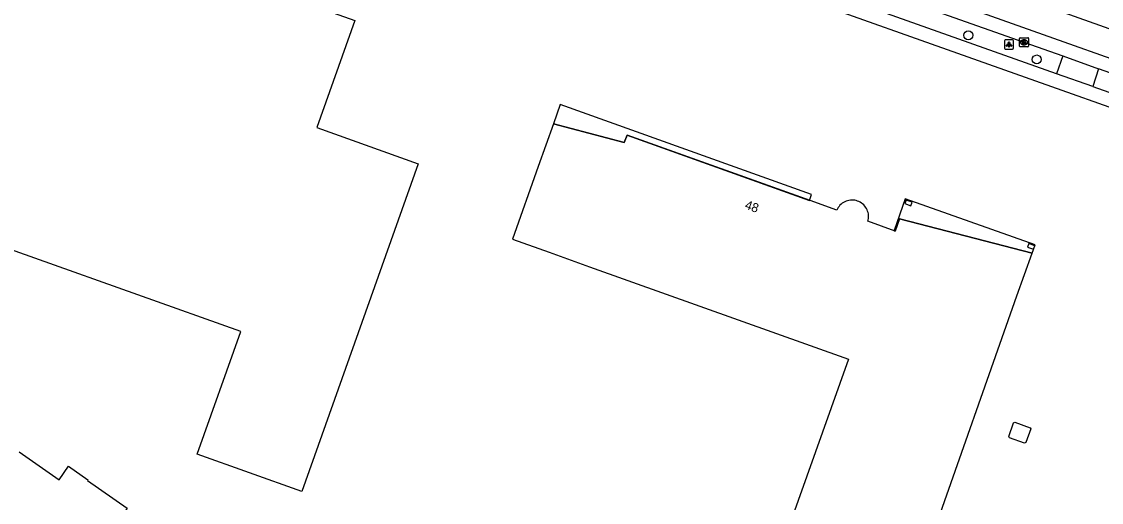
# Model space of a CAD drawing. Extents: x 155018 to 156648, y 383980 to 385733.
# Drawn here: x 155544.9 to 155664.5, y 385117.1 to 385170.3 of the extents above; entities that cross this region are included whole.
import ezdxf

# ---------------------------------------------------------------- set-up
doc = ezdxf.new("R2010")
doc.units = 0
for name, color, linetype in [('IMGEO_Boom', 7, 'Continuous'), ('IMGEO_Kolk', 7, 'Continuous'), ('IMGEO_Lage_trafo', 7, 'Continuous'), ('IMGEO_Lichtpunt', 7, 'Continuous'), ('IMGEO_OVBaan_gesloten', 7, 'Continuous'), ('IMGEO_Pand', 7, 'Continuous'), ('IMGEO_Pand_nummerreeks', 7, 'Continuous'), ('IMGEO_Pand_overbouw', 7, 'Continuous'), ('IMGEO_Rijbaan_lokaal_gesloten', 7, 'Continuous'), ('IMGEO_Rijbaan_lokaal_open', 7, 'Continuous'), ('IMGEO_Voetpad_open', 7, 'Continuous')]:
    doc.layers.add(name, color=color, linetype=linetype)

msp = doc.modelspace()

# ---------------------------------------------------------------- linework, layer by layer
at = {"layer": 'IMGEO_Boom'}
for centre in [(155649.75, 385168.83), (155657.32, 385166.16)]:
    msp.add_circle(centre, 0.489, dxfattribs=at)
at = {"layer": 'IMGEO_Kolk'}
for p, q in [((155655.41, 385167.63), (155655.41, 385168.49)), ((155655.49, 385168.56), (155656.34, 385168.56)), ((155656.34, 385167.56), (155655.49, 385167.56)), ((155655.9, 385168.34), (155655.93, 385168.34)), ((155655.92, 385167.78), (155655.9, 385167.78)), ((155656.41, 385168.49), (155656.41, 385167.63))]:
    msp.add_line(p, q, dxfattribs=at)
for points in [[(155655.41, 385167.63), (155655.41, 385168.49)], [(155655.49, 385168.56), (155656.34, 385168.56)], [(155656.34, 385167.56), (155655.49, 385167.56)], [(155655.73, 385168.26), (155655.86, 385168.26), (155655.86, 385168.11), (155655.99, 385168.26), (155656.15, 385168.26), (155656.01, 385168.11), (155656.16, 385167.86), (155656.01, 385167.86), (155655.92, 385168.02), (155655.86, 385167.96), (155655.86, 385167.86), (155655.73, 385167.86), (155655.73, 385168.26)], [(155656.41, 385168.49), (155656.41, 385167.63)]]:
    msp.add_lwpolyline(points, dxfattribs=at)
for centre, start, end in [((155655.49, 385168.48), 91.552, 178.448), ((155655.49, 385168.48), 91.552, 178.448), ((155655.49, 385167.63), 181.552, 268.448), ((155655.49, 385167.63), 181.552, 268.448), ((155656.34, 385168.48), 1.552, 88.448), ((155656.34, 385168.48), 1.552, 88.448), ((155656.34, 385167.63), 271.552, 358.448), ((155656.34, 385167.63), 271.552, 358.448)]:
    msp.add_arc(centre, 0.0765, start, end, dxfattribs=at)
for centre, major_axis, ratio, start_param, end_param in [((155655.9, 385168.06), (-0.387, 0.002), 0.722429, 4.712389, 7.853982), ((155655.92, 385168.06), (-0.39, 0.002), 0.717154, 1.570796, 4.712389)]:
    msp.add_ellipse(centre, major_axis=major_axis, ratio=ratio, start_param=start_param, end_param=end_param, dxfattribs=at)
at = {"layer": 'IMGEO_Lage_trafo'}
msp.add_lwpolyline([(155655.98, 385123.68), (155654.3, 385124.27), (155654.22, 385124.42), (155654.75, 385125.91), (155654.91, 385125.99), (155656.6, 385125.37), (155656.66, 385125.24), (155656.12, 385123.74), (155655.98, 385123.68)], dxfattribs=at)
at = {"layer": 'IMGEO_Lichtpunt'}
for p, q in [((155653.75, 385168.22), (155653.75, 385167.41)), ((155653.75, 385168.22), (155653.75, 385167.41)), ((155654.65, 385168.31), (155653.84, 385168.31)), ((155654.65, 385168.31), (155653.84, 385168.31)), ((155654.74, 385167.41), (155654.74, 385168.22)), ((155654.74, 385167.41), (155654.74, 385168.22)), ((155653.84, 385167.31), (155654.65, 385167.31)), ((155653.84, 385167.31), (155654.65, 385167.31))]:
    msp.add_line(p, q, dxfattribs=at)
for points in [[(155654.12, 385167.88), (155654.16, 385167.85), (155653.97, 385167.59), (155653.93, 385167.62), (155654.12, 385167.88)], [(155654.22, 385167.83), (155654.27, 385167.83), (155654.27, 385167.51), (155654.22, 385167.51), (155654.22, 385167.83)], [(155654.33, 385167.85), (155654.37, 385167.88), (155654.56, 385167.62), (155654.52, 385167.59), (155654.33, 385167.85)]]:
    msp.add_lwpolyline(points, dxfattribs=at)
msp.add_circle((155654.25, 385168.01), 0.0994, dxfattribs=at)
for centre, start, end in [((155653.84, 385168.22), 90, 180), ((155653.84, 385168.22), 90, 180), ((155653.84, 385167.41), 180, 270), ((155653.84, 385167.41), 180, 270), ((155654.65, 385168.22), 0, 90), ((155654.65, 385168.22), 0, 90), ((155654.65, 385167.41), 270, 0), ((155654.65, 385167.41), 270, 360)]:
    msp.add_arc(centre, 0.0946, start, end, dxfattribs=at)
at = {"layer": 'IMGEO_OVBaan_gesloten'}
msp.add_lwpolyline([(155740.67, 385142.78), (155686.14, 385162.15), (155622.86, 385184.67)], dxfattribs=at)
at = {"layer": 'IMGEO_Pand'}
for points in [[(155564.35, 385122.44), (155569.18, 385136.03), (155534.94, 385148.2), (155545.92, 385179.11), (155547.38, 385178.75), (155551.81, 385178.73), (155553.29, 385178.36), (155554, 385180.39), (155574.93, 385172.93), (155575.01, 385172.91), (155581.82, 385170.48), (155577.59, 385158.61), (155588.82, 385154.6), (155575.94, 385118.32), (155564.35, 385122.44)], [(155656.82, 385144.69), (155642.14, 385148.51), (155641.65, 385147.16), (155638.63, 385148.24), (155638.67, 385148.4), (155638.69, 385148.56), (155638.7, 385148.72), (155638.7, 385148.89), (155638.68, 385149.05), (155638.64, 385149.21), (155638.59, 385149.36), (155638.53, 385149.51), (155638.46, 385149.66), (155638.37, 385149.79), (155638.27, 385149.92), (155638.16, 385150.04), (155638.04, 385150.15), (155637.91, 385150.25), (155637.77, 385150.34), (155637.63, 385150.41), (155637.48, 385150.48), (155637.33, 385150.52), (155637.17, 385150.56), (155637, 385150.58), (155636.84, 385150.58), (155636.68, 385150.57), (155636.52, 385150.55), (155636.36, 385150.51), (155636.21, 385150.46), (155636.06, 385150.4), (155635.91, 385150.32), (155635.78, 385150.23), (155635.65, 385150.13), (155635.53, 385150.02), (155635.43, 385149.89), (155635.33, 385149.76), (155635.25, 385149.62), (155635.18, 385149.48), (155632.25, 385150.52), (155611.95, 385157.79), (155611.64, 385156.96), (155603.8, 385159.03), (155602.12, 385154.32), (155599.26, 385146.25), (155603.32, 385144.81), (155607.79, 385143.21), (155636.49, 385132.98), (155624.37, 385098.99)], [(155643.51, 385150.35), (155642.85, 385150.58), (155642.73, 385150.2), (155643.39, 385149.96), (155643.51, 385150.35)], [(155645.5, 385112.59), (155655.13, 385139.98), (155656.82, 385144.69)], [(155657.1, 385145.53), (155656.44, 385145.76), (155656.3, 385145.38), (155656.96, 385145.15), (155657.1, 385145.53)], [(155544.65, 385122.72), (155549.06, 385119.62), (155550.12, 385121.11), (155552.26, 385119.62), (155552.2, 385119.53), (155556.6, 385116.46), (155537.67, 385089.36)]]:
    msp.add_lwpolyline(points, dxfattribs=at)
at = {"layer": 'IMGEO_Pand_overbouw'}
for points in [[(155603.8, 385159.03), (155611.64, 385156.96), (155611.95, 385157.79), (155632.16, 385150.55), (155632.39, 385151.21), (155604.56, 385161.17)], [(155641.52, 385147.21), (155641.65, 385147.16), (155642.14, 385148.51), (155656.82, 385144.69), (155657.15, 385145.62), (155642.76, 385150.74)]]:
    msp.add_lwpolyline(points, close=True, dxfattribs=at)
at = {"layer": 'IMGEO_Rijbaan_lokaal_gesloten'}
for points in [[(155557.9, 385204.57), (155590.36, 385193.1), (155633.9, 385177.52), (155691.94, 385156.87), (155720.53, 385146.69), (155727.05, 385144.08), (155745.95, 385136.27), (155751.44, 385134.14), (155754.81, 385131.97), (155774.68, 385119.56)], [(155608.55, 385184.96), (155621.39, 385180.35), (155622.05, 385180.11), (155638.51, 385174.25), (155655.91, 385168.06), (155660.2, 385166.54)], [(155660.2, 385166.54), (155664.16, 385165.13)], [(155675.31, 385161.19), (155670.53, 385162.88), (155664.16, 385165.13)]]:
    msp.add_lwpolyline(points, dxfattribs=at)
at = {"layer": 'IMGEO_Rijbaan_lokaal_open'}
for points in [[(155660.2, 385166.54), (155659.51, 385164.58)], [(155664.16, 385165.13), (155663.52, 385163.16)], [(155663.52, 385163.16), (155659.51, 385164.58)]]:
    msp.add_lwpolyline(points, dxfattribs=at)
at = {"layer": 'IMGEO_Voetpad_open'}
for points in [[(155551.45, 385201.4), (155601.27, 385183.67), (155602.3, 385183.3), (155620.24, 385176.93), (155661.24, 385162.35), (155670.01, 385159.25), (155717.6, 385142.4), (155751.4, 385130.42)], [(155659.51, 385164.58), (155620.72, 385178.36), (155607.83, 385182.94)], [(155663.52, 385163.16), (155674.61, 385159.23)]]:
    msp.add_lwpolyline(points, dxfattribs=at)

# ---------------------------------------------------------------- texts
at = {"layer": 'IMGEO_Pand_nummerreeks'}
msp.add_text('48', height=1, rotation=340.3189, dxfattribs=at).set_placement((155624.92, 385149.66))

doc.saveas('drawing.dxf')
